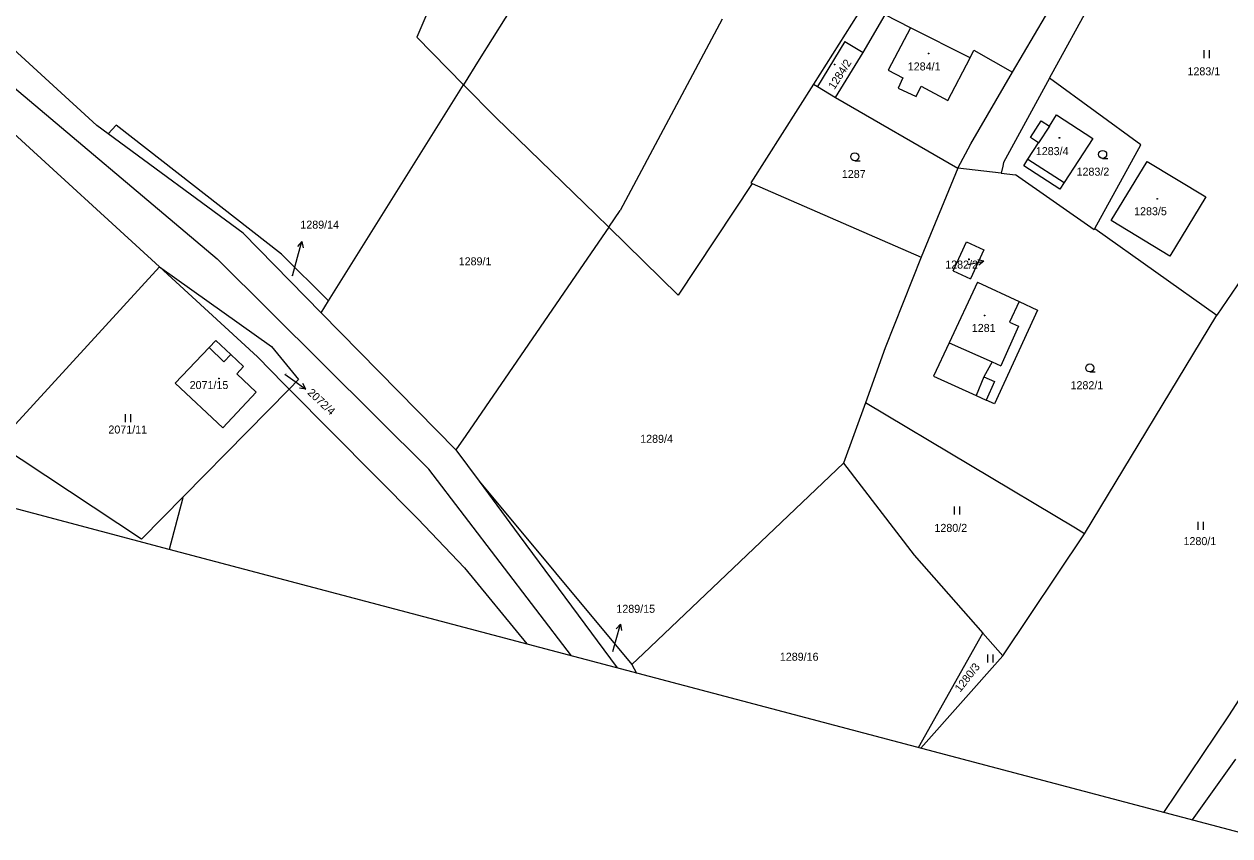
# Model space of a CAD drawing. Extents: x -805011 to -803920, y -1150790 to -1150234.
# Drawn here: x -804429.5 to -804203.4, y -1150736.4 to -1150584.2 of the extents above; entities that cross this region are included whole.
import ezdxf

# ---------------------------------------------------------------- set-up
doc = ezdxf.new("R2010")
doc.units = 0
for name, color, linetype in [('Default', 7, 'Continuous'), ('formát', 7, 'Continuous'), ('kn_celek - Cisla parcel pomocna', 7, 'Continuous'), ('kn_celek - Cisla pozemkovych parcel', 7, 'Continuous'), ('kn_celek - Cisla stavebnich parcel', 7, 'Continuous'), ('kn_celek - Hranice parcel', 7, 'Continuous'), ('kn_celek - Vnitrni kresby', 7, 'Continuous'), ('kn_celek - Znacky budov', 7, 'Continuous'), ('kn_celek - Znacky kultur', 7, 'Continuous')]:
    doc.layers.add(name, color=color, linetype=linetype)

# ---------------------------------------------------------------- blocks, each defined once
blk = doc.blocks.new('306')
at = {"layer": 'Default'}
for p, q in [((-5.2, 0), (-5.2, 15)), ((4.8, 0), (4.8, 15))]:
    blk.add_line(p, q, dxfattribs=at)
blk = doc.blocks.new('304')
at = {"layer": 'Default'}
blk.add_line((-0.1, 0), (9.9, 0), dxfattribs=at)
blk.add_circle((-0.1, 7.5), 7.5, dxfattribs=at)
blk = doc.blocks.new('402')
at = {"layer": 'Default'}
for p, q in [((-0.8, 0.8), (0.7, 0.8)), ((-0.8, 0.8), (-0.8, -0.7)), ((0.7, 0.8), (0.7, -0.7)), ((0.7, -0.7), (-0.8, -0.7))]:
    blk.add_line(p, q, dxfattribs=at)
blk = doc.blocks.new('Z61')
at = {"layer": 'Default'}
for p, q in [((0, 0), (30, 0)), ((30, 0), (19.2, 5.3)), ((30, 0), (19.2, -5.3))]:
    blk.add_line(p, q, dxfattribs=at)

msp = doc.modelspace()

# ---------------------------------------------------------------- linework, layer by layer
at = {"layer": 'formát'}
for p, q in [((-804402.28, -1150682.7), (-805011.32, -1150521.54)), ((-804399.72, -1150673.03), (-804402.28, -1150682.7)), ((-804399.72, -1150673.03), (-804402.28, -1150682.7)), ((-804199.27, -1150736.42), (-804402.28, -1150682.7))]:
    msp.add_line(p, q, dxfattribs=at)
at = {"layer": 'kn_celek - Cisla parcel pomocna'}
for p, q in [((-804379.16, -1150631.41), (-804378.19, -1150627.89)), ((-804380.58, -1150649.84), (-804379.07, -1150650.93)), ((-804319.12, -1150701.83), (-804318.49, -1150699.59))]:
    msp.add_line(p, q, dxfattribs=at)
at = {"layer": 'kn_celek - Hranice parcel'}
for p, q in [((-804282.73, -1150492.43), (-804344.13, -1150590.85)), ((-804237.26, -1150594.36), (-804210.52, -1150545.49)), ((-804244.16, -1150593.22), (-804225.71, -1150561.73)), ((-804353.79, -1150581.83), (-804355.87, -1150586.66)), ((-804271.97, -1150580.46), (-804281.49, -1150595.48)), ((-804298.61, -1150583.27), (-804317.72, -1150619.16)), ((-804272.21, -1150589.52), (-804268.04, -1150582.49)), ((-804263.3, -1150584.93), (-804268.04, -1150582.49)), ((-804415.85, -1150603.25), (-804436.08, -1150584.68)), ((-804252.15, -1150590.56), (-804263.3, -1150584.93)), ((-804440.13, -1150588.68), (-804393.29, -1150628.23)), ((-804355.87, -1150586.66), (-804347.09, -1150595.59)), ((-804344.13, -1150590.85), (-804347.09, -1150595.59)), ((-804277.39, -1150597.99), (-804272.21, -1150589.52)), ((-804252.15, -1150590.56), (-804251.42, -1150589.13)), ((-804251.42, -1150589.13), (-804244.16, -1150593.22)), ((-804252.02, -1150606.69), (-804244.16, -1150593.22)), ((-804281.49, -1150595.48), (-804293.22, -1150613.99)), ((-804281.49, -1150595.48), (-804280.75, -1150595.93)), ((-804237.26, -1150594.36), (-804245.9, -1150610.15)), ((-804220.16, -1150606.83), (-804237.26, -1150594.36)), ((-804372.38, -1150636.13), (-804347.09, -1150595.59)), ((-804347.09, -1150595.59), (-804341.03, -1150601.74)), ((-804280.75, -1150595.93), (-804277.39, -1150597.99)), ((-804277.39, -1150597.99), (-804254.42, -1150611.22)), ((-804178.44, -1150598.56), (-804205.91, -1150638.78)), ((-804341.03, -1150601.74), (-804322.29, -1150619.89)), ((-804237.27, -1150603.33), (-804235.92, -1150601.25)), ((-804235.92, -1150601.25), (-804229.1, -1150605.66)), ((-804432.9, -1150603.34), (-804404.11, -1150629.75)), ((-804413.73, -1150604.81), (-804415.85, -1150603.25)), ((-804412.2, -1150603.15), (-804413.73, -1150604.81)), ((-804381.23, -1150627.34), (-804412.2, -1150603.15)), ((-804240.82, -1150605.47), (-804238.79, -1150602.34)), ((-804238.79, -1150602.34), (-804237.27, -1150603.33)), ((-804388.4, -1150623.42), (-804413.73, -1150604.81)), ((-804254.42, -1150611.22), (-804252.02, -1150606.69)), ((-804241.29, -1150609.51), (-804239.3, -1150606.45)), ((-804239.3, -1150606.45), (-804240.82, -1150605.47)), ((-804229.1, -1150605.66), (-804234.48, -1150613.93)), ((-804228.77, -1150622.54), (-804220.16, -1150606.83)), ((-804254.42, -1150611.22), (-804261.34, -1150627.91)), ((-804246.31, -1150612.18), (-804254.42, -1150611.22)), ((-804246.03, -1150610.82), (-804246.31, -1150612.18)), ((-804245.9, -1150610.15), (-804246.03, -1150610.82)), ((-804242.07, -1150610.76), (-804241.29, -1150609.51)), ((-804235.3, -1150615.14), (-804242.07, -1150610.76)), ((-804225.68, -1150621.05), (-804218.96, -1150609.97)), ((-804218.96, -1150609.97), (-804207.96, -1150616.6)), ((-804246.31, -1150612.18), (-804243.63, -1150612.49)), ((-804228.89, -1150622.76), (-804243.63, -1150612.49)), ((-804292.99, -1150614.09), (-804306.85, -1150635.03)), ((-804293.22, -1150613.99), (-804292.99, -1150614.09)), ((-804292.99, -1150614.09), (-804261.34, -1150627.91)), ((-804234.48, -1150613.93), (-804235.3, -1150615.14)), ((-804207.96, -1150616.6), (-804214.72, -1150627.7)), ((-804322.29, -1150619.89), (-804319.86, -1150622.28)), ((-804319.86, -1150622.28), (-804317.72, -1150619.16)), ((-804319.86, -1150622.28), (-804323.16, -1150627.09)), ((-804319.86, -1150622.28), (-804306.85, -1150635.03)), ((-804228.77, -1150622.54), (-804228.89, -1150622.76)), ((-804228.77, -1150622.54), (-804205.91, -1150638.78)), ((-804214.72, -1150627.7), (-804225.68, -1150621.05)), ((-804388.4, -1150623.42), (-804373.76, -1150638.35)), ((-804323.16, -1150627.09), (-804346.67, -1150661.33)), ((-804255.3, -1150630.48), (-804252.79, -1150625.05)), ((-804252.79, -1150625.05), (-804249.58, -1150626.53)), ((-804249.58, -1150626.53), (-804252.07, -1150631.98)), ((-804353.61, -1150667.65), (-804393.29, -1150628.23)), ((-804372.38, -1150636.13), (-804381.23, -1150627.34)), ((-804261.34, -1150627.91), (-804268.04, -1150644.89)), ((-804434.49, -1150662.92), (-804404.11, -1150629.75)), ((-804404.11, -1150629.75), (-804385.72, -1150646.62)), ((-804404.11, -1150629.75), (-804383.09, -1150644.69)), ((-804255.3, -1150630.48), (-804252.07, -1150631.98)), ((-804250.77, -1150632.61), (-804256.07, -1150643.95)), ((-804250.77, -1150632.61), (-804242.93, -1150636.25)), ((-804373.76, -1150638.35), (-804372.38, -1150636.13)), ((-804348.53, -1150664.03), (-804373.76, -1150638.35)), ((-804239.52, -1150637.83), (-804247.58, -1150655.44)), ((-804242.93, -1150636.25), (-804239.52, -1150637.83)), ((-804230.67, -1150679.78), (-804205.91, -1150638.78)), ((-804401.13, -1150651.53), (-804394.8, -1150644.87)), ((-804394.8, -1150644.87), (-804393.54, -1150643.55)), ((-804393.54, -1150643.55), (-804390.73, -1150646.17)), ((-804383.09, -1150644.69), (-804378.02, -1150650.82)), ((-804268.04, -1150644.89), (-804271.76, -1150655.21)), ((-804256.07, -1150643.95), (-804259, -1150650.23)), ((-804390.73, -1150646.17), (-804388.33, -1150648.43)), ((-804385.72, -1150646.62), (-804380.78, -1150651.65)), ((-804388.33, -1150648.43), (-804389.59, -1150649.77)), ((-804392.24, -1150659.89), (-804401.13, -1150651.53)), ((-804389.59, -1150649.77), (-804385.94, -1150653.21)), ((-804379.79, -1150652.64), (-804380.78, -1150651.65)), ((-804378.02, -1150650.82), (-804379.79, -1150652.64)), ((-804259, -1150650.23), (-804251, -1150653.88)), ((-804379.79, -1150652.64), (-804407.44, -1150680.8)), ((-804385.94, -1150653.21), (-804392.24, -1150659.89)), ((-804355.66, -1150676.96), (-804379.79, -1150652.64)), ((-804251, -1150653.88), (-804249.13, -1150654.73)), ((-804271.76, -1150655.21), (-804275.84, -1150666.53)), ((-804232.39, -1150678.75), (-804271.76, -1150655.21)), ((-804247.58, -1150655.44), (-804249.13, -1150654.73)), ((-804407.44, -1150680.8), (-804434.49, -1150662.92)), ((-804346.67, -1150661.33), (-804348.53, -1150664.03)), ((-804348.53, -1150664.03), (-804344.19, -1150669.9)), ((-804326.84, -1150702.66), (-804353.61, -1150667.65)), ((-804275.84, -1150666.53), (-804313.36, -1150702.22)), ((-804275.84, -1150666.53), (-804262.64, -1150683.78)), ((-804344.19, -1150669.9), (-804336.65, -1150680.08)), ((-804344.19, -1150669.9), (-804315.52, -1150704.27)), ((-804355.66, -1150676.96), (-804346.94, -1150686.14)), ((-804230.67, -1150679.78), (-804232.39, -1150678.75)), ((-804336.65, -1150680.08), (-804318.28, -1150704.93)), ((-804245.97, -1150702.66), (-804230.67, -1150679.78)), ((-804262.64, -1150683.78), (-804249.73, -1150698.42)), ((-804346.94, -1150686.14), (-804335.24, -1150700.44)), ((-804203.66, -1150713.94), (-804191.87, -1150695.58)), ((-804261.8, -1150719.87), (-804249.73, -1150698.42)), ((-804245.97, -1150702.66), (-804249.73, -1150698.42)), ((-804313.36, -1150702.22), (-804315.52, -1150704.27)), ((-804245.97, -1150702.66), (-804261.39, -1150719.98)), ((-804315.52, -1150704.27), (-804314.65, -1150705.89)), ((-804215.84, -1150732.04), (-804203.66, -1150713.94)), ((-804202.38, -1150722.01), (-804210.52, -1150733.44))]:
    msp.add_line(p, q, dxfattribs=at)
at = {"layer": 'kn_celek - Vnitrni kresby'}
for p, q in [((-804263.3, -1150584.93), (-804267.51, -1150592.83)), ((-804275.61, -1150587.5), (-804280.75, -1150595.93)), ((-804275.61, -1150587.5), (-804272.21, -1150589.52)), ((-804256.28, -1150598.52), (-804252.15, -1150590.56)), ((-804267.51, -1150592.83), (-804264.74, -1150594.31)), ((-804264.74, -1150594.31), (-804265.64, -1150596.2)), ((-804265.64, -1150596.2), (-804262.27, -1150597.81)), ((-804262.27, -1150597.81), (-804261.34, -1150595.87)), ((-804261.34, -1150595.87), (-804256.28, -1150598.52)), ((-804237.27, -1150603.33), (-804239.3, -1150606.45)), ((-804241.29, -1150609.51), (-804234.48, -1150613.93)), ((-804242.93, -1150636.25), (-804244.72, -1150640.07)), ((-804244.72, -1150640.07), (-804243.08, -1150640.87)), ((-804243.08, -1150640.87), (-804246.35, -1150648.26)), ((-804392, -1150647.51), (-804394.8, -1150644.87)), ((-804256.07, -1150643.95), (-804247.99, -1150647.53)), ((-804390.73, -1150646.17), (-804392, -1150647.51)), ((-804247.99, -1150647.53), (-804249.54, -1150650.32)), ((-804247.99, -1150647.53), (-804246.35, -1150648.26)), ((-804249.54, -1150650.32), (-804251, -1150653.88)), ((-804249.54, -1150650.32), (-804247.54, -1150651.25)), ((-804247.54, -1150651.25), (-804249.13, -1150654.73))]:
    msp.add_line(p, q, dxfattribs=at)

# ---------------------------------------------------------------- block references
at = {"layer": 'kn_celek - Cisla parcel pomocna'}
for p, xscale, yscale, rotation in [((-804378.19, -1150627.89), 0.1, 0.10000000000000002, 74.56365000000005), ((-804252.48, -1150629.28), 0.09999999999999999, 0.10000000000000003, 11.310030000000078), ((-804379.07, -1150650.93), 0.1, 0.10000000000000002, -35.986769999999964), ((-804318.49, -1150699.59), 0.1, 0.10000000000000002, 74.21706000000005)]:
    msp.add_blockref('Z61', p, dxfattribs=dict(at, xscale=xscale, yscale=yscale, rotation=rotation))
at = {"layer": 'kn_celek - Znacky budov', "xscale": 0.1, "yscale": 0.10000000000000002}
for p in [(-804259.92, -1150589.73), (-804277.54, -1150591.78), (-804235.41, -1150605.54), (-804217.06, -1150616.98), (-804252.38, -1150628.33), (-804249.43, -1150638.86), (-804392.97, -1150650.67)]:
    msp.add_blockref('402', p, dxfattribs=at)
at = {"layer": 'kn_celek - Znacky kultur', "xscale": 0.1, "yscale": 0.10000000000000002}
for name, p in [('306', (-804207.77, -1150590.58)), ('304', (-804273.74, -1150609.83)), ('304', (-804227.28, -1150609.39)), ('304', (-804229.69, -1150649.43)), ('306', (-804409.94, -1150658.82)), ('306', (-804254.56, -1150676.17)), ('306', (-804208.89, -1150679.06)), ('306', (-804248.28, -1150703.92))]:
    msp.add_blockref(name, p, dxfattribs=at)

# ---------------------------------------------------------------- texts
at = {"layer": 'kn_celek - Cisla parcel pomocna'}
for s, p in [('1289/14', (-804377.68, -1150622.57)), ('1282/2', (-804256.8, -1150630.05)), ('1289/15', (-804318.44, -1150694.59))]:
    msp.add_text(s, height=1.5, dxfattribs=at).set_placement(p)
msp.add_text('2072/4', height=1.5, rotation=316.7211, dxfattribs=at).set_placement((-804376.47, -1150653.46))
at = {"layer": 'kn_celek - Cisla pozemkovych parcel'}
for s, height, p in [('1283/1', 1.5, (-804211.39, -1150593.82)), ('1283/2', 1.5, (-804232.18, -1150612.63)), ('1287', 1.5, (-804276.18, -1150613.07)), ('1289/1', 1.5, (-804348, -1150629.44)), ('1289/14', 0.1, (-804379.47, -1150631.38)), ('2072/4', 0.1, (-804380.58, -1150649.81)), ('1282/1', 1.5, (-804233.31, -1150652.67)), ('2071/11', 1.5, (-804413.66, -1150660.98)), ('1289/4', 1.5, (-804313.98, -1150662.72)), ('1280/2', 1.5, (-804258.82, -1150679.42)), ('1280/1', 1.5, (-804212.13, -1150681.9)), ('1289/15', 0.1, (-804319.42, -1150701.8)), ('1289/16', 1.5, (-804287.8, -1150703.58))]:
    msp.add_text(s, height=height, dxfattribs=at).set_placement(p)
msp.add_text('1280/3', height=1.5, rotation=51.8976, dxfattribs=at).set_placement((-804253.98, -1150709.58))
at = {"layer": 'kn_celek - Cisla stavebnich parcel'}
msp.add_text('1284/2', height=1.5, rotation=57.6, dxfattribs=at).set_placement((-804277.57, -1150596.6))
for s, height, p in [('1284/1', 1.5, (-804263.82, -1150592.9)), ('1283/4', 1.5, (-804239.82, -1150608.78)), ('1283/5', 1.5, (-804221.39, -1150620.05)), ('1282/2', 0.1, (-804252.48, -1150629.25)), ('1281', 1.5, (-804251.82, -1150641.93)), ('2071/15', 1.5, (-804398.43, -1150652.64))]:
    msp.add_text(s, height=height, dxfattribs=at).set_placement(p)

doc.saveas('drawing.dxf')
